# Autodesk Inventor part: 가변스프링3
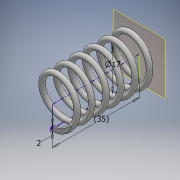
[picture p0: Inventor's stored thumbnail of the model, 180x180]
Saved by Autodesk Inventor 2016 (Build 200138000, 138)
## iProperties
Created: 2021-02
Part Number: 가변스프링3
Material: 일반
Document SubType Name: Modeling
Designer: Windows7
Density: 1 g/cm^3
Appearance: 기본값
Mass: 0.982159 g
Surface Area: 20.0174 cm^2
Volume: 0.982159 cm^3
Author: Windows7
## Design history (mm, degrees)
sketch "스케치1"
  geometry: L1 (0, 0)-(17, 0); L2 (17, 0)-(17, -8.5); L3 (17, -8.5)-(0, -8.5); L4 (0, -8.5)-(0, 0); C1 r 1 at (0, -8.5)
  constraints: 8 end point, 2 parallel, 1 centre point, 1 coincident, 1 horizontal, 1 perpendicular
  dimensions: "d0" = 2 diameter of C1; "d1" = 17 diameter of L3 L1; "d2" = 17 distance of L2.end L3.end (derived)
feature "코일1" pitch "d3" = 10; turns "d5" = 6; dims "d4" = 17 (= d2), "d6" = 0, angle "d7" = 90 deg, angle "d8" = 90 deg, "d9" = 0, "d10" = 0
feature "분할1"
node "작업 평면1"
feature "분할2"
node "솔리드1"
other parameters: "d11" = 90 deg
